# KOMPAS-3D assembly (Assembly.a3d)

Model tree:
1. Plane XY
2. Plane ZX
3. Plane ZY
4. X Axis
5. Y Axis
6. Z Axis
7. Origin
8. Pattern by Sample:1  (labels: Instance ( 1, 2 );; Instance ( 1, 3 );; Instance ( 1, 4 );; Instance ( 1, 5 );)

Referenced files in C:\Users\kashirsky.ASCONKLMN\Desktop\2010_04_28_Parametrisation\: Cover1.m3d|Flange_Diam, Cover1.m3d, Flange.m3d
Referenced files in C:\Users\kashirsky.ASCONKLMN\Desktop\: Part.m3d
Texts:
  Three Point Plane
  Plane at Angle
  Line and Point Plane
  Axis through Two Vertices
  Axis of Feature
  Axis of Conical Surface
  Axis through Edge
  Trim by Surface
  Trim by Sketch
  Intersection Axis of Two Planes
  Two Line Plane
  Line and Face Plane
  Pattern by Sample
  Point in CM
  Feature with No History
  Linear Dimension from Line to Point
  Surface Finish Symbol
  Geometric Tolerance Symbol
  Arc of Circle
  Junction of curves
  Array by nodes of sketch
  Leader #1
  Leader #2
  Leader #3
  Shape Deviations and Datum
  Node point number
  Mark of coordination axis
  Node point designation
  Mark/Reference designation with leader
  Mark/reference designation on line
  Mark/Reference designation without leader
  Instance ( 1, 2 );
  Instance ( 1, 3 );
  Instance ( 1, 4 );
  Instance ( 1, 5 );
  Instance ( 1, 6 );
